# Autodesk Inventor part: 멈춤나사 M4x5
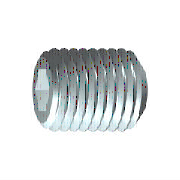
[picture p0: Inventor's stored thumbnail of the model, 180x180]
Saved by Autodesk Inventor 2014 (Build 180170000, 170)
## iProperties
IsCustomPart: 1
Created: 2012-02
Part Number: 멈춤나사 M4x5
Material: 강철, 연강
Description: 6각 소켓 머리 없는 멈춤 나사
Document SubType Name: Modeling
Standard: KS B 1028
Designer: mduedu
Standards Organization: KS
Language: ko-KR
Size Designation: 납작점M4x5
Categories: <MemberInstance><Categories><Category DisplayName="조임쇠" InternalName="e4da775c-781d-43d5-af7c-5136215cf5a6" Mnemonic="FSTN"><Category DisplayName="볼트" InternalN
Density: 1 g/cm^3
Appearance: Steel
Author: mduedu
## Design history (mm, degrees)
sketch "스케치1"
  geometry: L1 (0, 0)-(1.833, 0); L2 (5, 1.155)-(5, 2); L3 (5, 2)-(0, 2); L4 (5, 1.155)-(2.5, 1.155); L5 (2.5, 1.155)-(1.833, 0); L6 (0, -0.4)-(0, 2.4) reference; L7 (0, 2)-(0, 0)
  constraints: 13 end point, 3 parallel, 1 collinear, 1 perpendicular, 1 point on line
  dimensions: "d0" = 2.5 distance of L2.start L4.end (= INTI); "d1" = 60 deg angle of L5 L1; "d2" = 4 diameter of L3 L1 (= NND); "d3" = 2.3094 diameter of L4 L1 (= 1.1547 x SW); "d5" = 5 distance from line of L2 L3.end (= NLG)
revolve "본체" sketch "스케치1" stored, may be unused: angle "d6" = 90 deg
sketch "스케치2"
  geometry: L1 (-0.577, 1)-(0.577, 1); L2 (0.577, 1)-(1.155, 0); L3 (1.155, 0)-(0.577, -1); L4 (0.577, -1)-(-0.577, -1); L5 (-0.577, -1)-(-1.155, 0); L6 (-1.155, 0)-(-0.577, 1); A1 r 1.155 centre (0, 0) between (-0.577, 1) and (0.577, 1) reference; 2 further points
  constraints: 12 end point, 2 point on circle, 1 coincident, 1 horizontal, 11 other
extrude "슬롯" join sketch "스케치2" taper "d9" = 0 deg; stored distance "d21" = 10
workaxis "Work Axis1"
workplane "Work Plane1"
body "Solid1"
chamfer "모따기1" distance "d7" = 0.42941 (= -0.5 x GD1 + 0.5 x NND); stored, may be unused: angle "d8" = 45 deg (= FAWI), second distance "d29" = 0.42941 (= -0.5 x GD1 + 0.5 x NND)
feature "스레드" dims "d11" = 5 (= NLG), "d12" = 0
chamfer "모따기2" distance "d13" = 0.42941 (= -0.5 x GD1 + 0.5 x NND); stored, may be unused: angle "d14" = 45 deg (= FAWI), second distance "d30" = 0.42941 (= -0.5 x GD1 + 0.5 x NND)
other parameters: "NND" = 4 [user parameter; used in 5 equation terms], "NLG" = 5 [user parameter; used in 2 equation terms], "INTI" = 2.5 [user parameter; used in 1 equation term], "FAWI" = 45 deg [user parameter; used in 2 equation terms], "SW" = 2 [user parameter; used in 2 equation terms], "GD1" = 3.14117 (= THREADDIA - 1.2269 x PTC) [user parameter; used in 4 equation terms], "d4" = 0, "FAWI1" = 45 deg [user parameter], "d15" = 0, "d31" = 0, "GUL" = 0.42941 (= 0.61345 x PTC) [user parameter], "SPD" = 2.5 [user parameter], "TPU" = 14.28571 (computed from PTC) [user parameter], "TOA" = 30 deg [user parameter], "THREADDIA" = 4 [user parameter; used in 1 equation term], "PTC" = 0.7 [user parameter; used in 4 equation terms], "GAL" = 0.42941 (= 0.61345 x PTC) [user parameter], "E0" = 2.31 (= 1.155 x SW) [user parameter]
